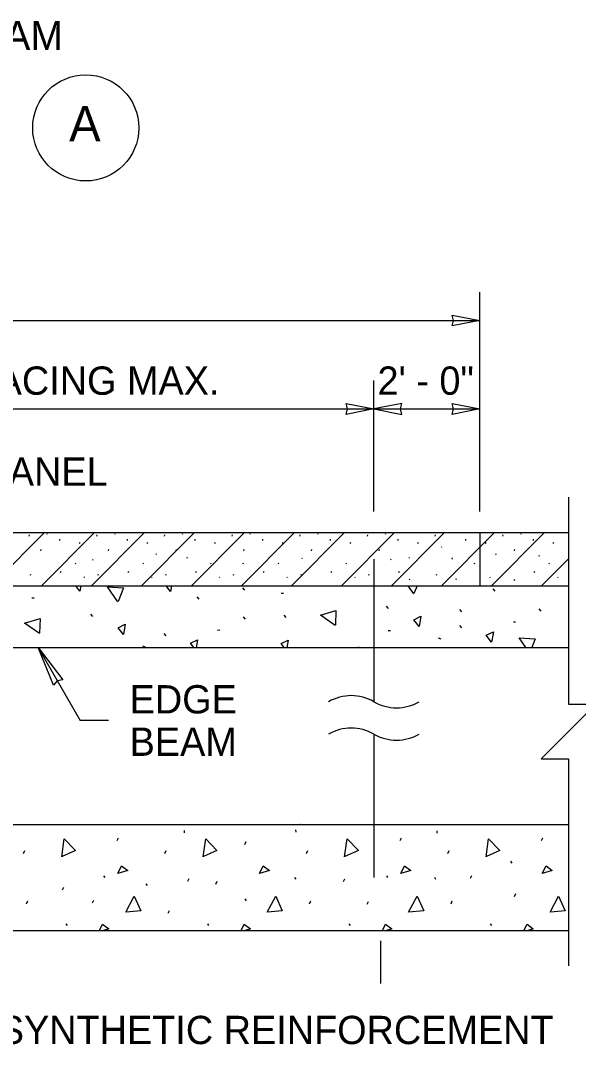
# Model space of a CAD drawing. Extents: x 99862 to 104211, y 98939 to 105076.
# Drawn here: x 101106 to 101422, y 103697 to 104276 of the extents above; entities that cross this region are included whole.
import ezdxf

# ---------------------------------------------------------------- set-up
doc = ezdxf.new("R2010")
doc.units = 0
for name, color, linetype in [('Level 10', 7, 'Continuous'), ('Level 12', 7, 'Continuous'), ('Level 15', 7, 'Continuous'), ('Level 20', 7, 'Continuous'), ('Level 26', 7, 'Continuous'), ('Level 3', 7, 'Continuous'), ('Level 6', 7, 'Continuous')]:
    doc.layers.add(name, color=color, linetype=linetype)

msp = doc.modelspace()

# ---------------------------------------------------------------- linework, layer by layer
at = {"layer": 'Level 10'}
for p, q in [((101306.13, 103971.29), (101306.13, 103890.67)), ((101306.13, 103872.35), (101306.13, 103791.29))]:
    msp.add_line(p, q, dxfattribs=at)
at = {"layer": 'Level 12'}
for p, q in [((100476.13, 103821.29), (101416.13, 103821.29)), ((100476.13, 103761.29), (101416.13, 103761.29))]:
    msp.add_line(p, q, dxfattribs=at)
at = {"layer": 'Level 15'}
for p, q in [((101366.13, 103998.29), (101366.13, 104122.29)), ((100526.13, 104106.29), (101366.13, 104106.29)), ((101306.13, 103998.29), (101306.13, 104072.29)), ((100586.13, 104056.29), (101306.13, 104056.29)), ((101306.13, 104056.29), (101366.13, 104056.29)), ((101116.2, 103921.29), (101140.01, 103880.04)), ((101156.01, 103880.04), (101140.01, 103880.04)), ((101309.88, 103755.38), (101309.88, 103731.38))]:
    msp.add_line(p, q, dxfattribs=at)
for points in [[(101366.13, 104106.29), (101350.41, 104103.21), (101351.14, 104106.29), (101350.41, 104109.37)], [(101306.13, 104056.29), (101290.41, 104053.21), (101291.14, 104056.29), (101290.41, 104059.37)], [(101306.13, 104056.29), (101321.86, 104053.21), (101321.13, 104056.29), (101321.86, 104059.37)], [(101366.13, 104056.29), (101350.41, 104053.21), (101351.14, 104056.29), (101350.41, 104059.37)], [(101116.2, 103921.29), (101130.2, 103903.01), (101127.08, 103902.43), (101125.03, 103900.03)]]:
    msp.add_lwpolyline(points, close=True, dxfattribs=at)
msp.add_lwpolyline([(101416.13, 104006.29), (101416.13, 103889.28), (101431.62, 103889.28), (101400.65, 103858.3), (101416.13, 103858.3), (101416.13, 103741.29)], dxfattribs=at)
for centre, start, end in [((101293.34, 103868.51), 60, 120), ((101318.93, 103912.83), 240, 300), ((101293.34, 103850.19), 60, 120), ((101318.93, 103894.51), 240, 300)]:
    msp.add_arc(centre, 25.59, start, end, dxfattribs=at)
at = {"layer": 'Level 20'}
msp.add_circle((101143.19, 104215.22), 30, dxfattribs=at)
at = {"layer": 'Level 26'}
for p, q in [((101089.81, 103956.29), (101119.81, 103986.29)), ((101111.18, 103984.4), (101111.46, 103985.04)), ((101118.1, 103956.29), (101148.1, 103986.29)), ((101121.16, 103985.79), (101121.44, 103985.36)), ((101128.28, 103982.59), (101128.35, 103981.94)), ((101146.38, 103956.29), (101176.38, 103986.29)), ((101149.44, 103984.4), (101149.73, 103985.04)), ((101159.42, 103985.79), (101159.71, 103985.36)), ((101166.54, 103982.59), (101166.61, 103981.94)), ((101174.67, 103956.29), (101204.67, 103986.29)), ((101187.7, 103984.4), (101187.99, 103985.04)), ((101197.68, 103985.79), (101197.97, 103985.36)), ((101202.95, 103956.29), (101232.95, 103986.29)), ((101204.81, 103982.59), (101204.88, 103981.94)), ((101225.97, 103984.4), (101226.26, 103985.04)), ((101231.24, 103956.29), (101261.24, 103986.29)), ((101235.95, 103985.79), (101236.24, 103985.36)), ((101243.07, 103982.59), (101243.14, 103981.94)), ((101259.52, 103956.29), (101289.52, 103986.29)), ((101264.23, 103984.4), (101264.52, 103985.04)), ((101274.21, 103985.79), (101274.5, 103985.36)), ((101281.33, 103982.59), (101281.41, 103981.94)), ((101287.8, 103956.29), (101317.8, 103986.29)), ((101302.5, 103984.4), (101302.78, 103985.04)), ((101312.48, 103985.79), (101312.76, 103985.36)), ((101316.09, 103956.29), (101346.09, 103986.29)), ((101319.6, 103982.59), (101319.67, 103981.94)), ((101340.76, 103984.4), (101341.05, 103985.04)), ((101344.37, 103956.29), (101374.37, 103986.29)), ((101357.86, 103982.59), (101357.93, 103981.94)), ((101372.66, 103956.29), (101402.66, 103986.29)), ((101379.02, 103984.4), (101379.31, 103985.04)), ((101389, 103985.79), (101389.29, 103985.36)), ((101396.13, 103982.59), (101396.2, 103981.94)), ((101117.72, 103976.05), (101118.01, 103976.7)), ((101139.55, 103980.68), (101139.84, 103980.25)), ((101155.99, 103976.05), (101156.27, 103976.7)), ((101177.82, 103980.68), (101178.11, 103980.25)), ((101194.25, 103976.05), (101194.54, 103976.7)), ((101216.08, 103980.68), (101216.37, 103980.25)), ((101232.51, 103976.05), (101232.8, 103976.7)), ((101254.35, 103980.68), (101254.63, 103980.25)), ((101270.78, 103976.05), (101271.07, 103976.7)), ((101292.61, 103980.68), (101292.9, 103980.25)), ((101309.04, 103976.05), (101309.33, 103976.7)), ((101330.87, 103980.68), (101331.16, 103980.25)), ((101344.11, 103978.45), (101344.4, 103978.02)), ((101369.14, 103980.68), (101369.43, 103980.25)), ((101385.57, 103976.05), (101385.86, 103976.7)), ((101407.4, 103980.68), (101407.69, 103980.25)), ((101147.09, 103971.08), (101147.38, 103970.65)), ((101182.92, 103974.33), (101183.2, 103973.89)), ((101200.33, 103972.34), (101200.61, 103971.91)), ((101265.35, 103972.08), (101265.64, 103971.64)), ((101315.57, 103971.39), (101315.86, 103970.96)), ((101325.98, 103972.25), (101326.27, 103971.82)), ((101350.35, 103971.32), (101350.64, 103971.96)), ((101374.83, 103974.47), (101375.12, 103974.03)), ((101399.35, 103973.49), (101399.64, 103973.06)), ((101400.94, 103956.29), (101416.13, 103971.48)), ((101128.94, 103963.85), (101129.23, 103964.5)), ((101137.28, 103969.02), (101137.57, 103968.59)), ((101167.21, 103963.85), (101167.49, 103964.5)), ((101175.55, 103969.02), (101175.83, 103968.59)), ((101205.47, 103963.85), (101205.76, 103964.5)), ((101213.81, 103969.02), (101214.1, 103968.59)), ((101231.98, 103969.18), (101232.27, 103968.75)), ((101243.73, 103963.85), (101244.02, 103964.5)), ((101252.08, 103969.02), (101252.36, 103968.59)), ((101282, 103963.85), (101282.29, 103964.5)), ((101290.34, 103969.02), (101290.63, 103968.59)), ((101320.26, 103963.85), (101320.55, 103964.5)), ((101362.77, 103969.18), (101363.06, 103968.75)), ((101396.79, 103963.85), (101397.08, 103964.5)), ((101405.13, 103969.02), (101405.42, 103968.59)), ((101111.89, 103962.2), (101112.18, 103962.84)), ((101142.11, 103961.36), (101142.4, 103960.92)), ((101150.16, 103962.2), (101150.45, 103962.84)), ((101180.37, 103961.36), (101180.66, 103960.92)), ((101188.42, 103962.2), (101188.71, 103962.84)), ((101218.64, 103961.36), (101218.92, 103960.92)), ((101226.69, 103962.2), (101226.97, 103962.84)), ((101256.9, 103961.36), (101257.19, 103960.92)), ((101264.95, 103962.2), (101265.24, 103962.84)), ((101295.16, 103961.36), (101295.45, 103960.92)), ((101303.21, 103962.2), (101303.5, 103962.84)), ((101326.18, 103960.07), (101326.47, 103959.64)), ((101341.48, 103962.2), (101341.77, 103962.84)), ((101352.66, 103959.74), (101352.95, 103960.39)), ((101371.69, 103961.36), (101371.98, 103960.92)), ((101385.48, 103959.17), (101385.77, 103959.82)), ((101409.96, 103961.36), (101410.24, 103960.92)), ((101233.07, 103953.73), (101231.96, 103955.09)), ((101374.68, 103953.22), (101373.58, 103954.58)), ((101112.68, 103949.35), (101113.95, 103949.5)), ((101207.37, 103948.68), (101206.27, 103950.04)), ((101253.69, 103952), (101254.96, 103952.14)), ((101314.44, 103943.36), (101313.34, 103944.72)), ((101355.94, 103941.56), (101354.83, 103942.92)), ((101400.79, 103941.91), (101399.69, 103943.27)), ((101147.14, 103938.82), (101146.03, 103940.18)), ((101233.48, 103937.37), (101232.38, 103938.73)), ((101256.46, 103938.23), (101255.36, 103939.59)), ((101385.01, 103935.77), (101386.28, 103935.92)), ((101188.63, 103927.94), (101187.53, 103929.29)), ((101217.7, 103931.23), (101218.97, 103931.38)), ((101314.21, 103930.87), (101315.49, 103931.02)), ((101355.94, 103932.47), (101354.83, 103933.83)), ((101342.51, 103926.89), (101344.02, 103926.32)), ((101175.2, 103922.35), (101176.71, 103921.78)), ((101297.81, 103921.29), (101297.46, 103921.72)), ((101161.01, 103812.12), (101161.72, 103813.72)), ((101198.79, 103817.8), (101198.94, 103816.46)), ((101261.78, 103818.16), (101261.93, 103816.82)), ((101321.01, 103812.12), (101321.72, 103813.72)), ((101341.68, 103817.62), (101341.83, 103816.27)), ((101401.01, 103812.12), (101401.72, 103813.72)), ((101233.23, 103809.94), (101233.94, 103811.54)), ((101108.01, 103804.83), (101108.72, 103806.43)), ((101188.01, 103804.83), (101188.72, 103806.43)), ((101268.01, 103804.83), (101268.72, 103806.43)), ((101348.01, 103804.83), (101348.72, 103806.43)), ((101383.47, 103800.44), (101384.18, 103799.37)), ((101153.22, 103792.23), (101153.93, 103791.16)), ((101200.88, 103789.15), (101201.59, 103790.74)), ((101261.22, 103791.33), (101261.93, 103790.27)), ((101288.99, 103788.95), (101289.71, 103790.55)), ((101313.22, 103792.23), (101313.93, 103791.16)), ((101340.34, 103791.37), (101341.05, 103790.31)), ((101360.81, 103790.82), (101361.53, 103792.41)), ((101130.03, 103784.23), (101130.74, 103785.83)), ((101177.14, 103787.71), (101177.85, 103786.64)), ((101216.77, 103787.52), (101217.48, 103789.12)), ((101147, 103776.89), (101147.72, 103778.49)), ((101233.22, 103779.13), (101233.93, 103778.07)), ((101385.68, 103780.52), (101386.39, 103782.12)), ((101109.78, 103776.44), (101110.49, 103778.04)), ((101269.78, 103776.44), (101270.49, 103778.04)), ((101302.33, 103776.14), (101303.05, 103777.74)), ((101349.78, 103776.44), (101350.49, 103778.04)), ((101189.78, 103770.98), (101190.49, 103772.58)), ((101131.98, 103765.07), (101132.69, 103764.01)), ((101211.98, 103765.07), (101212.69, 103764.01)), ((101291.98, 103765.07), (101292.69, 103764.01)), ((101371.98, 103765.07), (101372.69, 103764.01))]:
    msp.add_line(p, q, dxfattribs=at)
for points in [[(101139.91, 103953.16), (101137.52, 103956.29)], [(101140.44, 103956.29), (101139.91, 103953.16)], [(101161.37, 103947.21), (101155.48, 103955.59), (101164.61, 103955.12), (101161.45, 103947.36)], [(101191.14, 103953.01), (101188.63, 103956.29)], [(101191.69, 103956.29), (101191.14, 103953.01)], [(101328.68, 103951.74), (101325.49, 103956.29)], [(101330.54, 103956.29), (101328.76, 103951.9)], [(101284.31, 103933.73), (101275.91, 103939.59), (101284.65, 103942.28), (101284.34, 103933.91)], [(101117.01, 103929.19), (101108.6, 103935.05), (101117.34, 103937.74), (101117.03, 103929.37)], [(101331.76, 103933.14), (101328.77, 103937.06), (101332.76, 103939.01), (101331.76, 103933.14)], [(101164.45, 103928.61), (101161.46, 103932.52), (101165.45, 103934.47), (101164.45, 103928.61)], [(101372.71, 103924.32), (101369.73, 103928.24), (101373.71, 103930.19), (101372.71, 103924.32)], [(101204.26, 103921.29), (101202.42, 103923.7), (101206.4, 103925.66), (101205.66, 103921.29)], [(101255.37, 103921.29), (101253.64, 103923.55), (101257.63, 103925.51), (101256.91, 103921.29)], [(101392.12, 103921.29), (101388.28, 103926.76), (101397.41, 103926.29), (101395.38, 103921.29)], [(101184.49, 103821.27), (101184.5, 103821.29)], [(101184.57, 103821.29), (101184.49, 103821.27)], [(101264.49, 103821.27), (101264.5, 103821.29)], [(101264.57, 103821.29), (101264.49, 103821.27)], [(101129.61, 103803), (101131.02, 103813.15), (101137.38, 103806.58), (101129.78, 103803.06)], [(101209.61, 103803), (101211.02, 103813.15), (101217.38, 103806.58), (101209.78, 103803.06)], [(101289.61, 103803), (101291.02, 103813.15), (101297.38, 103806.58), (101289.78, 103803.06)], [(101369.61, 103803), (101371.02, 103813.15), (101377.38, 103806.58), (101369.78, 103803.06)], [(101161.37, 103793.47), (101163.5, 103797.91), (101167.05, 103795.24), (101161.37, 103793.47)], [(101241.37, 103793.47), (101243.5, 103797.91), (101247.05, 103795.24), (101241.37, 103793.47)], [(101321.37, 103793.47), (101323.5, 103797.91), (101327.05, 103795.24), (101321.37, 103793.47)], [(101401.37, 103793.47), (101403.5, 103797.91), (101407.05, 103795.24), (101401.37, 103793.47)], [(101165.81, 103771.65), (101170.6, 103780.7), (101174.33, 103772.36), (101165.98, 103771.65)], [(101245.81, 103771.65), (101250.6, 103780.7), (101254.33, 103772.36), (101245.98, 103771.65)], [(101325.81, 103771.65), (101330.6, 103780.7), (101334.33, 103772.36), (101325.98, 103771.65)], [(101405.81, 103771.65), (101410.6, 103780.7), (101414.33, 103772.36), (101405.98, 103771.65)], [(101151.03, 103761.29), (101152.76, 103764.9), (101156.31, 103762.23), (101153.3, 103761.29)], [(101231.03, 103761.29), (101232.76, 103764.9), (101236.31, 103762.23), (101233.3, 103761.29)], [(101311.03, 103761.29), (101312.76, 103764.9), (101316.31, 103762.23), (101313.3, 103761.29)], [(101391.03, 103761.29), (101392.76, 103764.9), (101396.31, 103762.23), (101393.3, 103761.29)]]:
    msp.add_lwpolyline(points, dxfattribs=at)
at = {"layer": 'Level 3'}
for p, q in [((100476.13, 103986.29), (101416.13, 103986.29)), ((101366.13, 103986.29), (101366.13, 103956.29)), ((100476.13, 103956.29), (101416.13, 103956.29))]:
    msp.add_line(p, q, dxfattribs=at)
at = {"layer": 'Level 6'}
msp.add_line((100476.13, 103921.29), (101416.13, 103921.29), dxfattribs=at)

# ---------------------------------------------------------------- texts
at = {"layer": 'Level 20'}
for s, height, p in [('EDGE BEAM', 16.5, (100999.09, 104259.24)), ('A', 20, (101133.8, 104207.6)), ('7/8" DIAM. GALV. ANCHOR ROD @ 4\' - 0\' SPACING MAX.', 16, (100649.9, 104064.29)), ('2\' - 0"', 16, (101308.2, 104064.29))]:
    msp.add_text(s, height=height, dxfattribs=at).set_placement(p)
for s, p in [('PRECAST CONCRETE FASCIA PANEL', (100769.2, 104012.83)), ('EDGE', (101168.01, 103884.04)), ('BEAM', (101168.01, 103860.04)), ('GEOSYNTHETIC REINFORCEMENT', (101046.45, 103697))]:
    msp.add_text(s, height=16, rotation=360, dxfattribs=at).set_placement(p)

doc.saveas('drawing.dxf')
